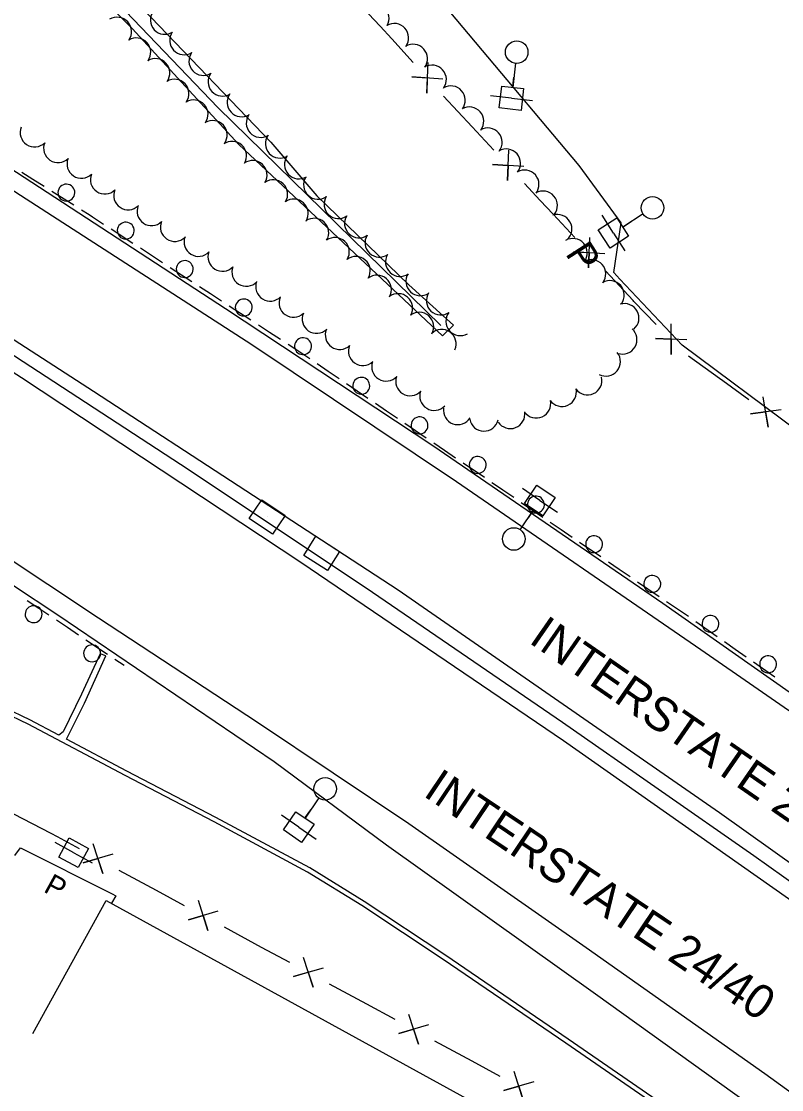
# Model space of a CAD drawing. Extents: x 1746010 to 1754829, y 655801 to 663091.
# Drawn here: x 1747673.4 to 1747943.2, y 661903.4 to 662282.7 of the extents above; entities that cross this region are included whole.
import ezdxf

# ---------------------------------------------------------------- set-up
doc = ezdxf.new("R2010")
doc.units = 0
for name, color, linetype in [('SURVEY - AERIAL SURVEY - Photo Control - Points - Elevations', 7, 'Continuous'), ('SURVEY - AERIAL SURVEY - Photo Control - Points - Locators', 7, 'Continuous'), ('SURVEY - AERIAL SURVEY - Photo Control - Points - Numbers', 7, 'Continuous'), ('SURVEY - CENTERLINE - Existing Roads - Development', 7, 'Continuous'), ('SURVEY - CENTERLINE - Existing Roads Curve Text', 7, 'Continuous'), ('SURVEY - CENTERLINE - Existing Roads Text', 7, 'Continuous'), ('SURVEY - CENTERLINE - Preliminary - Development', 7, 'Continuous'), ('SURVEY - CONTROL - Grid', 7, 'Continuous'), ('SURVEY - CONTROL - Points - Numbers', 7, 'Continuous')]:
    doc.layers.add(name, color=color, linetype=linetype)

msp = doc.modelspace()

# ---------------------------------------------------------------- linework, layer by layer
at = {"layer": 'SURVEY - AERIAL SURVEY - Photo Control - Points - Elevations'}
for points in [[(1747602.4, 662403.5), (1747669.23, 662335.35), (1747719.55, 662284.11), (1747761.96, 662239.85), (1747778.3, 662220.7), (1747810.93, 662189.19), (1747826.76, 662174.79), (1747822.89, 662171.03), (1747750.67, 662239.02), (1747712.71, 662280.14), (1747659.71, 662333.11), (1747612.9, 662380.42), (1747595.99, 662398.49)], [(1747985.76, 661838.11), (1747954.49, 661859.84), (1747913.88, 661887.28), (1747866.65, 661919.88), (1747823.19, 661949.53), (1747794.28, 661968.76), (1747775.03, 661980.63), (1747741.82, 661998.46), (1747710.25, 662014.92), (1747675.84, 662033.13), (1747649.1, 662045.94), (1747622.01, 662057.94), (1747602.48, 662067.13), (1747603.06, 662068.67)], [(1747686.7, 662029.24), (1747676.47, 662034.65), (1747649.67, 662047.49), (1747622.57, 662059.5), (1747603.06, 662068.67)], [(1747986.63, 661839.49), (1747955.35, 661861.23), (1747914.73, 661888.68), (1747867.51, 661921.26), (1747824.03, 661950.93), (1747795.08, 661970.18), (1747775.76, 661982.1), (1747742.5, 661999.96), (1747710.92, 662016.42), (1747689.43, 662027.8), (1747695.86, 662040.62), (1747703.39, 662057.35), (1747701.38, 662058.12), (1747694.8, 662043.74), (1747688.3, 662030.46), (1747686.7, 662029.24)]]:
    msp.add_lwpolyline(points, dxfattribs=at)
at = {"layer": 'SURVEY - AERIAL SURVEY - Photo Control - Points - Locators'}
for points in [[(1747886.26, 662211.22), (1747871.44, 662231.56), (1747834.62, 662275.31), (1747794.68, 662323), (1747775.79, 662345.64), (1747759.61, 662364.42), (1747733.67, 662396.93)], [(1748066.62, 661959.87), (1747978.51, 662021.63), (1747901.08, 662075.95), (1747819.42, 662131.94), (1747745.85, 662180.6), (1747671.72, 662228.98), (1747613.87, 662265.2), (1747545.13, 662307.66)], [(1748067.96, 661950.85), (1747977.15, 662016.22), (1747914.56, 662059.52), (1747827.89, 662119.16), (1747755.21, 662167.87), (1747663.67, 662226.9), (1747617.46, 662256.37), (1747540.61, 662304.67)], [(1747500.14, 662277.89), (1747606.38, 662211.23), (1747699.06, 662151.4), (1747807.18, 662080.79), (1747921.23, 662001.72), (1748045.01, 661913.44)], [(1748036.84, 661905.72), (1747955.58, 661964.08), (1747865.84, 662027.24), (1747772.62, 662090.53), (1747673.46, 662156.1), (1747599.02, 662204.01), (1747520.15, 662254.13), (1747491.6, 662272.24)], [(1747449.54, 662244.42), (1747495.25, 662212.96), (1747544.44, 662177.78), (1747597.81, 662139.99), (1747646.37, 662106.97), (1747700.87, 662070.9), (1747757.2, 662033.9), (1747810.92, 661997.83), (1747873.88, 661953.8), (1747937.26, 661909.07), (1748007.34, 661858.36)], [(1747447.41, 662243.01), (1747476.14, 662221.97), (1747510.35, 662195.13), (1747548.92, 662165.86), (1747597.25, 662131.99), (1747654.78, 662092.84), (1747686.43, 662071.96), (1747763.1, 662019.85), (1747803.08, 661990.33), (1747877.22, 661937.39), (1747950.5, 661884.69), (1747998.74, 661850.34)], [(1748111.68, 662015.71), (1748050.02, 662061.42), (1747985, 662109.76), (1747949.2, 662136.91), (1747907.89, 662167.74), (1747885.82, 662191.19), (1747883.71, 662193.54), (1747886.26, 662211.22)], [(1747671.1, 661986.48), (1747673.09, 661989.24), (1747705.69, 661972.83), (1747706.92, 661972.21), (1747705.44, 661969.51)]]:
    msp.add_lwpolyline(points, dxfattribs=at)
at = {"layer": 'SURVEY - AERIAL SURVEY - Photo Control - Points - Numbers'}
for points in [[(1747495.88, 662275.08), (1747565, 662231.38), (1747654.17, 662174.84), (1747729.86, 662125.51), (1747795.86, 662081.53), (1747865.54, 662033.9), (1747933.39, 661986.48), (1748007.95, 661933.43), (1748040.01, 661910.33)], [(1747677.56, 662226.54), (1747673.58, 662229.05)], [(1747681.54, 662224.04), (1747677.56, 662226.54)], [(1747692.03, 662217.43), (1747684.24, 662222.33)], [(1747698.7, 662213.2), (1747697.49, 662213.98), (1747694.73, 662215.72)], [(1747702.64, 662210.63), (1747698.7, 662213.2)], [(1747713.02, 662203.87), (1747705.31, 662208.89)], [(1747719.64, 662199.55), (1747715.7, 662202.12)], [(1747723.58, 662196.99), (1747719.64, 662199.55)], [(1747733.96, 662190.22), (1747726.26, 662195.24)], [(1747740.58, 662185.91), (1747736.64, 662188.47)], [(1747744.52, 662183.34), (1747740.58, 662185.91)], [(1747754.91, 662176.58), (1747747.2, 662181.6)], [(1747761.52, 662172.27), (1747757.59, 662174.83)], [(1747765.46, 662169.7), (1747761.52, 662172.27)], [(1747775.78, 662162.83), (1747770.83, 662166.2), (1747768.14, 662167.95)], [(1747782.31, 662158.39), (1747778.43, 662161.04)], [(1747786.2, 662155.75), (1747782.31, 662158.39)], [(1747796.45, 662148.78), (1747788.84, 662153.95)], [(1747802.98, 662144.34), (1747799.1, 662146.98)], [(1747806.87, 662141.69), (1747802.98, 662144.34)], [(1747817.12, 662134.72), (1747809.52, 662139.9)], [(1747823.65, 662130.28), (1747819.77, 662132.92)], [(1747827.54, 662127.64), (1747823.65, 662130.28)], [(1747837.79, 662120.67), (1747830.19, 662125.84)], [(1747844.32, 662116.22), (1747842.47, 662117.49), (1747840.44, 662118.87)], [(1747848.2, 662113.57), (1747844.32, 662116.22)], [(1747858.45, 662106.58), (1747850.85, 662111.77)], [(1747864.97, 662102.13), (1747861.09, 662104.78)], [(1747868.86, 662099.48), (1747864.97, 662102.13)], [(1747879.1, 662092.5), (1747871.5, 662097.68)], [(1747885.63, 662088.04), (1747881.75, 662090.69)], [(1747889.51, 662085.4), (1747885.63, 662088.04)], [(1747899.75, 662078.41), (1747892.15, 662083.59)], [(1747675.55, 662077.03), (1747679.7, 662074.27), (1747683.2, 662071.92)], [(1747906.28, 662073.95), (1747902.4, 662076.6)], [(1747910.16, 662071.31), (1747906.28, 662073.95)], [(1747685.86, 662070.14), (1747689.76, 662067.53)], [(1747689.76, 662067.53), (1747693.67, 662064.91)], [(1747920.32, 662064.2), (1747912.8, 662069.49)], [(1747696.32, 662063.13), (1747703.97, 662058.01)], [(1747926.79, 662059.66), (1747922.94, 662062.36)], [(1747930.63, 662056.95), (1747926.79, 662059.66)], [(1747706.62, 662056.22), (1747709.88, 662054.05)], [(1747940.78, 662049.83), (1747933.25, 662055.11)]]:
    msp.add_lwpolyline(points, dxfattribs=at)
for centre, start, end in [((1747689.43, 662221.9), 346.8702, 346.8562), ((1747710.48, 662208.39), 346.0222, 346.0082), ((1747731.42, 662194.74), 346.0222, 346.0082), ((1747752.37, 662181.1), 346.0222, 346.0082), ((1747773.4, 662167.36), 344.6849, 344.6709), ((1747794.07, 662153.3), 344.6849, 344.6709), ((1747814.74, 662139.25), 344.6849, 344.6709), ((1747835.41, 662125.19), 344.6849, 344.6709), ((1747856.04, 662111.13), 344.6768, 344.6628), ((1747876.7, 662097.04), 344.6768, 344.6628), ((1747897.35, 662082.95), 344.6768, 344.6628), ((1747677.79, 662072.18), 168.186, 168.172), ((1747917.99, 662068.77), 343.8574, 343.8435), ((1747698.54, 662058.28), 167.9697, 167.9558), ((1747938.45, 662054.4), 343.8574, 343.8435)]:
    msp.add_arc(centre, 3, start, end, dxfattribs=at)
at = {"layer": 'SURVEY - CENTERLINE - Existing Roads - Development'}
for points in [[(1747804.86, 662276.52), (1747800.76, 662281.06), (1747794.65, 662287.46)], [(1747812.48, 662268.08), (1747804.86, 662276.52)], [(1747823.07, 662262.2), (1747812.01, 662263.05), (1747817.51, 662262.66), (1747817.29, 662257.2), (1747817.79, 662268.05)], [(1747833.39, 662245.22), (1747823.26, 662256.15), (1747823.25, 662256.16)], [(1747841.1, 662236.91), (1747833.39, 662245.22)], [(1747851.76, 662231.17), (1747840.65, 662231.92), (1747846.17, 662231.58), (1747845.99, 662226.16), (1747846.42, 662236.93)], [(1747862.12, 662214.23), (1747857.6, 662219.11), (1747851.98, 662225.17)], [(1747869.81, 662205.91), (1747862.12, 662214.23)], [(1747880.48, 662200.16), (1747869.36, 662200.92), (1747874.89, 662200.58), (1747874.7, 662195.16), (1747875.14, 662205.92)], [(1747890.83, 662183.22), (1747890.53, 662183.53), (1747880.69, 662194.16)], [(1747898.77, 662175.07), (1747890.83, 662183.22)], [(1747909.56, 662169.6), (1747898.48, 662170.03), (1747903.99, 662169.85), (1747903.99, 662164.38), (1747904.06, 662175.24)], [(1747922.38, 662155.1), (1747921.25, 662155.93), (1747910.24, 662163.86)], [(1747931.56, 662148.35), (1747922.38, 662155.1)], [(1747943.09, 662144.72), (1747932.16, 662143.31), (1747937.58, 662144.04), (1747938.52, 662138.63), (1747936.72, 662149.4)], [(1747684.01, 661994.26), (1747670.81, 662001.23)], [(1747694.03, 661988.86), (1747686.23, 661993.08), (1747684.01, 661994.26)], [(1747705.87, 661986.94), (1747695.36, 661983.88), (1747700.57, 661985.43), (1747702.3, 661980.12), (1747698.93, 661990.69)], [(1747721.35, 661974.08), (1747708.17, 661981.21)], [(1747731.37, 661968.66), (1747721.35, 661974.08)], [(1747677.56, 661923.28), (1747703.56, 661970.54), (1747923.57, 661849.49), (1747897.62, 661802.32)], [(1747743.21, 661966.74), (1747732.7, 661963.68), (1747737.91, 661965.23), (1747739.64, 661959.92), (1747736.27, 661970.49)], [(1747758.69, 661953.88), (1747745.51, 661961.01)], [(1747768.71, 661948.46), (1747758.69, 661953.88)], [(1747780.55, 661946.53), (1747770.04, 661943.47), (1747775.25, 661945.03), (1747776.98, 661939.72), (1747773.61, 661950.29)], [(1747796.03, 661933.68), (1747782.85, 661940.81)], [(1747806.05, 661928.26), (1747796.03, 661933.68)], [(1747817.89, 661926.33), (1747807.38, 661923.27), (1747812.59, 661924.83), (1747814.32, 661919.52), (1747810.95, 661930.08)], [(1747833.38, 661913.45), (1747820.19, 661920.6)], [(1747843.4, 661908.02), (1747833.38, 661913.45)], [(1747855.28, 661906.07), (1747844.71, 661903.05), (1747849.95, 661904.58), (1747851.65, 661899.29), (1747848.34, 661909.83)]]:
    msp.add_lwpolyline(points, dxfattribs=at)
at = {"layer": 'SURVEY - CENTERLINE - Existing Roads Curve Text'}
for p, q in [((1747848.79, 662267.92), (1747847.8, 662259.27)), ((1747847.85, 662259.67), (1747848.21, 662262.85)), ((1747847.36, 662255.4), (1747839.91, 662256.25)), ((1747847.36, 662255.4), (1747854.81, 662254.55)), ((1747894.16, 662214.36), (1747886.85, 662209.65)), ((1747883.57, 662207.54), (1747879.51, 662213.85)), ((1747887.18, 662209.87), (1747889.87, 662211.6)), ((1747883.57, 662207.54), (1747887.63, 662201.24)), ((1747857.47, 662112.57), (1747851.26, 662116.77)), ((1747857.47, 662112.57), (1747863.68, 662108.36)), ((1747850.4, 662102.13), (1747855.28, 662109.34)), ((1747855.06, 662109.01), (1747853.26, 662106.35)), ((1747779.03, 662006.95), (1747774.1, 661999.79)), ((1747774.33, 662000.12), (1747776.14, 662002.75)), ((1747771.89, 661996.58), (1747765.71, 662000.83)), ((1747771.89, 661996.58), (1747778.07, 661992.32)), ((1747692.01, 661987.48), (1747685.43, 661991.09)), ((1747692.01, 661987.48), (1747698.58, 661983.87))]:
    msp.add_line(p, q, dxfattribs=at)
for points in [[(1747843.04, 662251.97), (1747843.93, 662259.72), (1747851.68, 662258.83), (1747850.79, 662251.08)], [(1747878.18, 662208.71), (1747884.74, 662212.93), (1747888.96, 662206.38), (1747882.4, 662202.15)], [(1747862.88, 662113.61), (1747858.51, 662107.15), (1747852.05, 662111.52), (1747856.42, 662117.98)], [(1747766.47, 661995.57), (1747770.89, 662002), (1747777.31, 661997.58), (1747772.89, 661991.15)], [(1747690.46, 661992.78), (1747697.3, 661989.02), (1747693.55, 661982.19), (1747686.71, 661985.94)]]:
    msp.add_lwpolyline(points, close=True, dxfattribs=at)
for centre in [(1747849.23, 662271.79), (1747897.44, 662216.48), (1747848.22, 662098.9), (1747781.25, 662010.17)]:
    msp.add_circle(centre, 4, dxfattribs=at)
at = {"layer": 'SURVEY - CENTERLINE - Existing Roads Text'}
for centre, start, end in [((1747724.35, 662283.24), 144.9851, 301.7785), ((1747798.78, 662283.8), 330.2115, 127.005), ((1747707.43, 662279.04), 324.3704, 121.1638), ((1747731.22, 662275.97), 144.9851, 301.7785), ((1747805.75, 662276.84), 323.6826, 120.476), ((1747714.22, 662271.7), 324.3704, 121.1638), ((1747738.04, 662268.65), 144.3225, 301.1159), ((1747812.44, 662269.45), 323.6826, 120.476), ((1747721, 662264.36), 324.3704, 121.1638), ((1747819.14, 662262.05), 323.6826, 120.476), ((1747744.82, 662261.3), 144.3225, 301.1159), ((1747727.79, 662257.02), 324.3704, 121.1638), ((1747825.84, 662254.65), 323.6826, 120.476), ((1747751.61, 662253.96), 144.3225, 301.1159), ((1747734.57, 662249.68), 324.3704, 121.1638), ((1747832.41, 662247.22), 322.6906, 119.4841), ((1747758.39, 662246.61), 144.3225, 301.1159), ((1747678.15, 662243.24), 157.7008, 314.4942), ((1747741.36, 662242.35), 324.3704, 121.1638), ((1747838.95, 662239.74), 322.6906, 119.4841), ((1747765.17, 662239.27), 144.3225, 301.1159), ((1747686.46, 662237.67), 157.7008, 314.4942), ((1747748.23, 662234.98), 328.4761, 125.2696), ((1747845.48, 662232.26), 322.6906, 119.4841), ((1747694.77, 662232.11), 157.7008, 314.4942), ((1747755.52, 662228.15), 328.4761, 125.2696), ((1747771.95, 662231.92), 144.3225, 301.1159), ((1747852.01, 662224.78), 322.6906, 119.4841), ((1747703.07, 662226.53), 157.3667, 314.1601), ((1747762.81, 662221.32), 328.4761, 125.2696), ((1747778.73, 662224.67), 148.2968, 305.0903), ((1747711.34, 662220.92), 157.3667, 314.1601), ((1747858.55, 662217.3), 322.6906, 119.4841), ((1747770.11, 662214.48), 328.4761, 125.2696), ((1747785.99, 662217.81), 148.2968, 305.0903), ((1747719.62, 662215.3), 157.3667, 314.1601), ((1747863.68, 662208.99), 311.3621, 108.1555), ((1747727.89, 662209.69), 157.3667, 314.1601), ((1747777.4, 662207.65), 328.4761, 125.2696), ((1747793.26, 662210.96), 148.2968, 305.0903), ((1747800.52, 662204.11), 148.2968, 305.0903), ((1747736.32, 662204.38), 159.4957, 316.2891), ((1747784.7, 662200.82), 328.4761, 125.2696), ((1747869.14, 662200.48), 322.8419, 119.6353), ((1747744.79, 662199.08), 159.4957, 316.2891), ((1747792.11, 662194.07), 330.3354, 127.1289), ((1747807.79, 662197.26), 148.2968, 305.0903), ((1747753.27, 662193.78), 159.4957, 316.2891), ((1747875.71, 662193), 322.8419, 119.6353), ((1747799.63, 662187.47), 330.3354, 127.1289), ((1747815.05, 662190.41), 148.2968, 305.0903), ((1747761.75, 662188.48), 159.4957, 316.2891), ((1747882.28, 662185.52), 322.8419, 119.6353), ((1747770.01, 662182.76), 156.6397, 313.4332), ((1747807.15, 662180.88), 330.3354, 127.1289), ((1747822.32, 662183.56), 148.2968, 305.0903), ((1747887.48, 662177.35), 310.319, 107.1124), ((1747778.22, 662177.04), 156.6397, 313.4332), ((1747814.66, 662174.28), 330.3354, 127.1289), ((1747829.24, 662176.24), 142.6942, 299.4876), ((1747786.42, 662171.33), 156.6397, 313.4332), ((1747822.6, 662168.17), 336.393, 133.1865), ((1747886.77, 662169.68), 251.765, 48.5584), ((1747794.63, 662165.61), 156.6397, 313.4332), ((1747880.92, 662161.88), 241.7432, 38.5366), ((1747802.89, 662160.09), 160.1141, 316.9076), ((1747811.43, 662154.89), 160.1141, 316.9076), ((1747874.37, 662155.19), 215.8674, 12.6608), ((1747819.96, 662149.68), 160.1141, 316.9076), ((1747865.28, 662151.09), 215.8674, 12.6608), ((1747856.18, 662146.99), 215.8674, 12.6608), ((1747828.34, 662144.63), 171.4902, 328.2836), ((1747847, 662143.21), 212.8512, 9.6447), ((1747837.61, 662142.32), 190.2245, 347.0179)]:
    msp.add_arc(centre, 5.13, start, end, dxfattribs=at)
at = {"layer": 'SURVEY - CENTERLINE - Preliminary - Development'}
for p, q in [((1747760.66, 662106.72), (1747760.66, 662106.72)), ((1747780, 662093.78), (1747780, 662093.78))]:
    msp.add_line(p, q, dxfattribs=at)
for points in [[(1747754.28, 662106.19), (1747758.75, 662112.83), (1747767.04, 662107.24), (1747762.57, 662100.61), (1747754.28, 662106.19)], [(1747773.63, 662093.08), (1747777.92, 662099.84), (1747786.36, 662094.48), (1747782.08, 662087.72), (1747773.63, 662093.08)]]:
    msp.add_lwpolyline(points, dxfattribs=at)
at = {"layer": 'SURVEY - CONTROL - Grid'}
msp.add_lwpolyline([(1747595.43, 662406.32), (1747743.33, 662251.96), (1747822.36, 662174.68)], dxfattribs=at)

# ---------------------------------------------------------------- texts
at = {"layer": 'SURVEY - CENTERLINE - Existing Roads Curve Text'}
for height, rotation, p in [(10, 302.7796, (1747866.28, 662200.22)), (7.48, 331.2365, (1747680.96, 661973.81))]:
    msp.add_text('P', height=height, rotation=rotation, dxfattribs=at).set_placement(p)
at = {"layer": 'SURVEY - CONTROL - Points - Numbers'}
for rotation, p in [(325.269, (1747853.16, 662062.3)), (326.1225, (1747815.67, 662007.89))]:
    msp.add_text('INTERSTATE 24/40', height=12, rotation=rotation, dxfattribs=at).set_placement(p)

doc.saveas('drawing.dxf')
